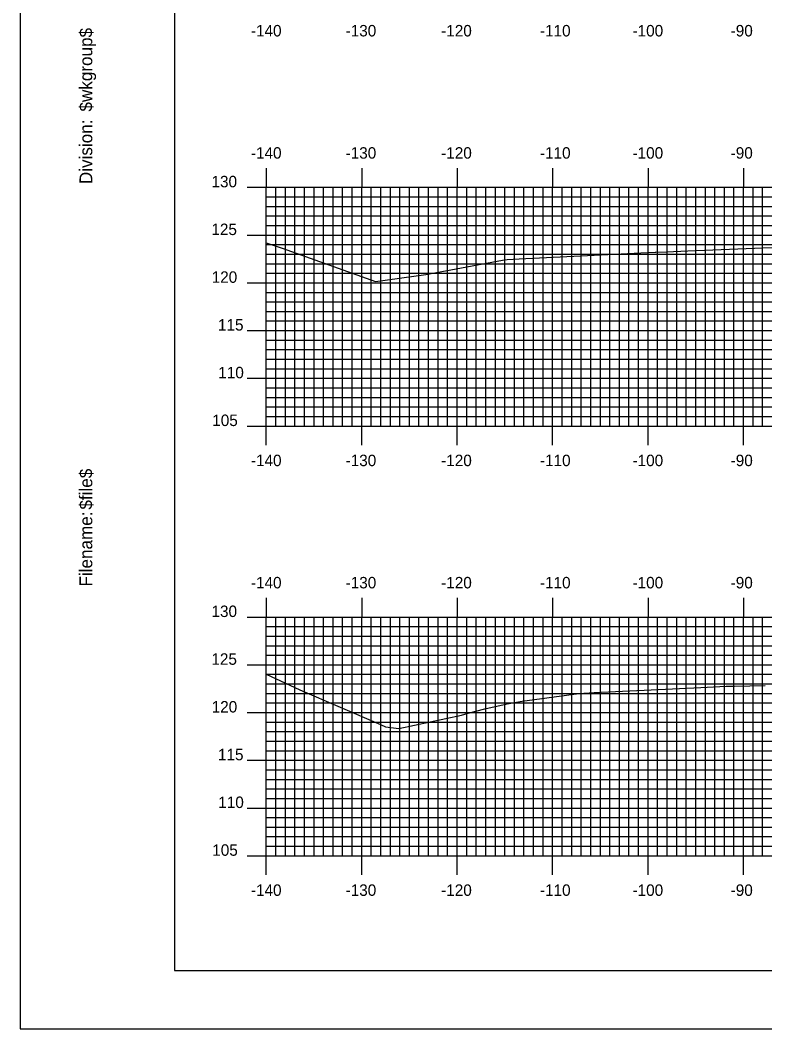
# Model space of a CAD drawing. Extents: x 854287 to 854631, y 366605 to 366825.
# Drawn here: x 854287.3 to 854365.3, y 366604.9 to 366710.6 of the extents above; entities that cross this region are included whole.
import ezdxf

# ---------------------------------------------------------------- set-up
doc = ezdxf.new("R2010")
doc.units = 0
for name, color, linetype in [('BORDER', 7, 'Continuous'), ('H_V ANNOTATION', 7, 'Continuous'), ('M_Roadway_Centerline', 7, 'Continuous'), ('MAJOR', 7, 'Continuous'), ('MINOR', 7, 'Continuous'), ('PLOT BOUNDARY', 7, 'Continuous'), ('S_Roadway_Centerline', 7, 'Continuous')]:
    doc.layers.add(name, color=color, linetype=linetype)

msp = doc.modelspace()

# ---------------------------------------------------------------- linework, layer by layer
at = {"layer": 'BORDER'}
msp.add_lwpolyline([(854303.44, 366611.06), (854623.44, 366611.06), (854623.44, 366821.06), (854303.44, 366821.06)], close=True, dxfattribs=at)
at = {"layer": 'MAJOR'}
for p, q in [((854313.04, 366695.06), (854313.04, 366693.06)), ((854323.04, 366695.06), (854323.04, 366693.06)), ((854333.04, 366695.06), (854333.04, 366693.06)), ((854343.04, 366695.06), (854343.04, 366693.06)), ((854353.04, 366695.06), (854353.04, 366693.06)), ((854363.04, 366695.06), (854363.04, 366693.06)), ((854311.04, 366693.06), (854313.04, 366693.06)), ((854313.04, 366693.06), (854593.04, 366693.06)), ((854313.04, 366668.06), (854313.04, 366693.06)), ((854313.04, 366668.06), (854313.04, 366693.06)), ((854313.04, 366693.06), (854593.04, 366693.06)), ((854323.04, 366668.06), (854323.04, 366693.06)), ((854333.04, 366668.06), (854333.04, 366693.06)), ((854343.04, 366668.06), (854343.04, 366693.06)), ((854353.04, 366668.06), (854353.04, 366693.06)), ((854363.04, 366668.06), (854363.04, 366693.06)), ((854311.04, 366688.06), (854313.04, 366688.06)), ((854313.04, 366688.06), (854593.04, 366688.06)), ((854311.04, 366683.06), (854313.04, 366683.06)), ((854313.04, 366683.06), (854593.04, 366683.06)), ((854311.04, 366678.06), (854313.04, 366678.06)), ((854313.04, 366678.06), (854593.04, 366678.06)), ((854311.04, 366673.06), (854313.04, 366673.06)), ((854313.04, 366673.06), (854593.04, 366673.06)), ((854311.04, 366668.06), (854313.04, 366668.06)), ((854313.04, 366668.06), (854593.04, 366668.06)), ((854313.04, 366668.06), (854593.04, 366668.06)), ((854313.04, 366666.05), (854313.04, 366668.06)), ((854323.04, 366666.05), (854323.04, 366668.06)), ((854333.04, 366666.05), (854333.04, 366668.06)), ((854343.04, 366666.05), (854343.04, 366668.06)), ((854353.04, 366666.05), (854353.04, 366668.06)), ((854363.04, 366666.05), (854363.04, 366668.06)), ((854313.04, 366650.06), (854313.04, 366648.06)), ((854323.04, 366650.06), (854323.04, 366648.06)), ((854333.04, 366650.06), (854333.04, 366648.06)), ((854343.04, 366650.06), (854343.04, 366648.06)), ((854353.04, 366650.06), (854353.04, 366648.06)), ((854363.04, 366650.06), (854363.04, 366648.06)), ((854311.04, 366648.06), (854313.04, 366648.06)), ((854313.04, 366648.06), (854593.04, 366648.06)), ((854313.04, 366623.06), (854313.04, 366648.06)), ((854313.04, 366623.06), (854313.04, 366648.06)), ((854313.04, 366648.06), (854593.04, 366648.06)), ((854323.04, 366623.06), (854323.04, 366648.06)), ((854333.04, 366623.06), (854333.04, 366648.06)), ((854343.04, 366623.06), (854343.04, 366648.06)), ((854353.04, 366623.06), (854353.04, 366648.06)), ((854363.04, 366623.06), (854363.04, 366648.06)), ((854311.04, 366643.06), (854313.04, 366643.06)), ((854313.04, 366643.06), (854593.04, 366643.06)), ((854311.04, 366638.06), (854313.04, 366638.06)), ((854313.04, 366638.06), (854593.04, 366638.06)), ((854311.04, 366633.06), (854313.04, 366633.06)), ((854313.04, 366633.06), (854593.04, 366633.06)), ((854311.04, 366628.06), (854313.04, 366628.06)), ((854313.04, 366628.06), (854593.04, 366628.06)), ((854311.04, 366623.06), (854313.04, 366623.06)), ((854313.04, 366623.06), (854593.04, 366623.06)), ((854313.04, 366623.06), (854593.04, 366623.06)), ((854313.04, 366621.05), (854313.04, 366623.06)), ((854323.04, 366621.05), (854323.04, 366623.06)), ((854333.04, 366621.05), (854333.04, 366623.06)), ((854343.04, 366621.05), (854343.04, 366623.06)), ((854353.04, 366621.05), (854353.04, 366623.06)), ((854363.04, 366621.05), (854363.04, 366623.06))]:
    msp.add_line(p, q, dxfattribs=at)
at = {"layer": 'MINOR'}
for p, q in [((854314.04, 366668.06), (854314.04, 366693.06)), ((854315.04, 366668.06), (854315.04, 366693.06)), ((854316.04, 366668.06), (854316.04, 366693.06)), ((854317.04, 366668.06), (854317.04, 366693.06)), ((854318.04, 366668.06), (854318.04, 366693.06)), ((854319.04, 366668.06), (854319.04, 366693.06)), ((854320.04, 366668.06), (854320.04, 366693.06)), ((854321.04, 366668.06), (854321.04, 366693.06)), ((854322.04, 366668.06), (854322.04, 366693.06)), ((854324.04, 366668.06), (854324.04, 366693.06)), ((854325.04, 366668.06), (854325.04, 366693.06)), ((854326.04, 366668.06), (854326.04, 366693.06)), ((854327.04, 366668.06), (854327.04, 366693.06)), ((854328.04, 366668.06), (854328.04, 366693.06)), ((854329.04, 366668.06), (854329.04, 366693.06)), ((854330.04, 366668.06), (854330.04, 366693.06)), ((854331.04, 366668.06), (854331.04, 366693.06)), ((854332.04, 366668.06), (854332.04, 366693.06)), ((854334.04, 366668.06), (854334.04, 366693.06)), ((854335.04, 366668.06), (854335.04, 366693.06)), ((854336.04, 366668.06), (854336.04, 366693.06)), ((854337.04, 366668.06), (854337.04, 366693.06)), ((854338.04, 366668.06), (854338.04, 366693.06)), ((854339.04, 366668.06), (854339.04, 366693.06)), ((854340.04, 366668.06), (854340.04, 366693.06)), ((854341.04, 366668.06), (854341.04, 366693.06)), ((854342.04, 366668.06), (854342.04, 366693.06)), ((854344.04, 366668.06), (854344.04, 366693.06)), ((854345.04, 366668.06), (854345.04, 366693.06)), ((854346.04, 366668.06), (854346.04, 366693.06)), ((854347.04, 366668.06), (854347.04, 366693.06)), ((854348.04, 366668.06), (854348.04, 366693.06)), ((854349.04, 366668.06), (854349.04, 366693.06)), ((854350.04, 366668.06), (854350.04, 366693.06)), ((854351.04, 366668.06), (854351.04, 366693.06)), ((854352.04, 366668.06), (854352.04, 366693.06)), ((854354.04, 366668.06), (854354.04, 366693.06)), ((854355.04, 366668.06), (854355.04, 366693.06)), ((854356.04, 366668.06), (854356.04, 366693.06)), ((854357.04, 366668.06), (854357.04, 366693.06)), ((854358.04, 366668.06), (854358.04, 366693.06)), ((854359.04, 366668.06), (854359.04, 366693.06)), ((854360.04, 366668.06), (854360.04, 366693.06)), ((854361.04, 366668.06), (854361.04, 366693.06)), ((854362.04, 366668.06), (854362.04, 366693.06)), ((854364.04, 366668.06), (854364.04, 366693.06)), ((854365.04, 366668.06), (854365.04, 366693.06)), ((854313.04, 366692.06), (854593.04, 366692.06)), ((854313.04, 366692.06), (854315.05, 366692.06)), ((854313.04, 366691.06), (854593.04, 366691.06)), ((854313.04, 366691.06), (854315.05, 366691.06)), ((854313.04, 366690.06), (854593.04, 366690.06)), ((854313.04, 366690.06), (854315.05, 366690.06)), ((854313.04, 366689.06), (854593.04, 366689.06)), ((854313.04, 366689.06), (854315.05, 366689.06)), ((854313.04, 366687.06), (854593.04, 366687.06)), ((854313.04, 366687.06), (854315.05, 366687.06)), ((854313.04, 366686.06), (854593.04, 366686.06)), ((854313.04, 366686.06), (854315.05, 366686.06)), ((854313.04, 366685.06), (854593.04, 366685.06)), ((854313.04, 366685.06), (854315.05, 366685.06)), ((854313.04, 366684.06), (854593.04, 366684.06)), ((854313.04, 366684.06), (854315.05, 366684.06)), ((854313.04, 366682.06), (854593.04, 366682.06)), ((854313.04, 366682.06), (854315.05, 366682.06)), ((854313.04, 366681.06), (854593.04, 366681.06)), ((854313.04, 366681.06), (854315.05, 366681.06)), ((854313.04, 366680.06), (854593.04, 366680.06)), ((854313.04, 366680.06), (854315.05, 366680.06)), ((854313.04, 366679.06), (854593.04, 366679.06)), ((854313.04, 366679.06), (854315.05, 366679.06)), ((854313.04, 366677.06), (854593.04, 366677.06)), ((854313.04, 366677.06), (854315.05, 366677.06)), ((854313.04, 366676.06), (854593.04, 366676.06)), ((854313.04, 366676.06), (854315.05, 366676.06)), ((854313.04, 366675.06), (854593.04, 366675.06)), ((854313.04, 366675.06), (854315.05, 366675.06)), ((854313.04, 366674.06), (854593.04, 366674.06)), ((854313.04, 366674.06), (854315.05, 366674.06)), ((854313.04, 366672.06), (854593.04, 366672.06)), ((854313.04, 366672.06), (854315.05, 366672.06)), ((854313.04, 366671.06), (854593.04, 366671.06)), ((854313.04, 366671.06), (854315.05, 366671.06)), ((854313.04, 366670.06), (854593.04, 366670.06)), ((854313.04, 366670.06), (854315.05, 366670.06)), ((854313.04, 366669.06), (854593.04, 366669.06)), ((854313.04, 366669.06), (854315.05, 366669.06)), ((854314.04, 366623.06), (854314.04, 366648.06)), ((854315.04, 366623.06), (854315.04, 366648.06)), ((854316.04, 366623.06), (854316.04, 366648.06)), ((854317.04, 366623.06), (854317.04, 366648.06)), ((854318.04, 366623.06), (854318.04, 366648.06)), ((854319.04, 366623.06), (854319.04, 366648.06)), ((854320.04, 366623.06), (854320.04, 366648.06)), ((854321.04, 366623.06), (854321.04, 366648.06)), ((854322.04, 366623.06), (854322.04, 366648.06)), ((854324.04, 366623.06), (854324.04, 366648.06)), ((854325.04, 366623.06), (854325.04, 366648.06)), ((854326.04, 366623.06), (854326.04, 366648.06)), ((854327.04, 366623.06), (854327.04, 366648.06)), ((854328.04, 366623.06), (854328.04, 366648.06)), ((854329.04, 366623.06), (854329.04, 366648.06)), ((854330.04, 366623.06), (854330.04, 366648.06)), ((854331.04, 366623.06), (854331.04, 366648.06)), ((854332.04, 366623.06), (854332.04, 366648.06)), ((854334.04, 366623.06), (854334.04, 366648.06)), ((854335.04, 366623.06), (854335.04, 366648.06)), ((854336.04, 366623.06), (854336.04, 366648.06)), ((854337.04, 366623.06), (854337.04, 366648.06)), ((854338.04, 366623.06), (854338.04, 366648.06)), ((854339.04, 366623.06), (854339.04, 366648.06)), ((854340.04, 366623.06), (854340.04, 366648.06)), ((854341.04, 366623.06), (854341.04, 366648.06)), ((854342.04, 366623.06), (854342.04, 366648.06)), ((854344.04, 366623.06), (854344.04, 366648.06)), ((854345.04, 366623.06), (854345.04, 366648.06)), ((854346.04, 366623.06), (854346.04, 366648.06)), ((854347.04, 366623.06), (854347.04, 366648.06)), ((854348.04, 366623.06), (854348.04, 366648.06)), ((854349.04, 366623.06), (854349.04, 366648.06)), ((854350.04, 366623.06), (854350.04, 366648.06)), ((854351.04, 366623.06), (854351.04, 366648.06)), ((854352.04, 366623.06), (854352.04, 366648.06)), ((854354.04, 366623.06), (854354.04, 366648.06)), ((854355.04, 366623.06), (854355.04, 366648.06)), ((854356.04, 366623.06), (854356.04, 366648.06)), ((854357.04, 366623.06), (854357.04, 366648.06)), ((854358.04, 366623.06), (854358.04, 366648.06)), ((854359.04, 366623.06), (854359.04, 366648.06)), ((854360.04, 366623.06), (854360.04, 366648.06)), ((854361.04, 366623.06), (854361.04, 366648.06)), ((854362.04, 366623.06), (854362.04, 366648.06)), ((854364.04, 366623.06), (854364.04, 366648.06)), ((854365.04, 366623.06), (854365.04, 366648.06)), ((854313.04, 366647.06), (854593.04, 366647.06)), ((854313.04, 366647.06), (854315.05, 366647.06)), ((854313.04, 366646.06), (854593.04, 366646.06)), ((854313.04, 366646.06), (854315.05, 366646.06)), ((854313.04, 366645.06), (854593.04, 366645.06)), ((854313.04, 366645.06), (854315.05, 366645.06)), ((854313.04, 366644.06), (854593.04, 366644.06)), ((854313.04, 366644.06), (854315.05, 366644.06)), ((854313.04, 366642.06), (854593.04, 366642.06)), ((854313.04, 366642.06), (854315.05, 366642.06)), ((854313.04, 366641.06), (854593.04, 366641.06)), ((854313.04, 366641.06), (854315.05, 366641.06)), ((854313.04, 366640.06), (854593.04, 366640.06)), ((854313.04, 366640.06), (854315.05, 366640.06)), ((854313.04, 366639.06), (854593.04, 366639.06)), ((854313.04, 366639.06), (854315.05, 366639.06)), ((854313.04, 366637.06), (854593.04, 366637.06)), ((854313.04, 366637.06), (854315.05, 366637.06)), ((854313.04, 366636.06), (854593.04, 366636.06)), ((854313.04, 366636.06), (854315.05, 366636.06)), ((854313.04, 366635.06), (854593.04, 366635.06)), ((854313.04, 366635.06), (854315.05, 366635.06)), ((854313.04, 366634.06), (854593.04, 366634.06)), ((854313.04, 366634.06), (854315.05, 366634.06)), ((854313.04, 366632.06), (854593.04, 366632.06)), ((854313.04, 366632.06), (854315.05, 366632.06)), ((854313.04, 366631.06), (854593.04, 366631.06)), ((854313.04, 366631.06), (854315.05, 366631.06)), ((854313.04, 366630.06), (854593.04, 366630.06)), ((854313.04, 366630.06), (854315.05, 366630.06)), ((854313.04, 366629.06), (854593.04, 366629.06)), ((854313.04, 366629.06), (854315.05, 366629.06)), ((854313.04, 366627.06), (854593.04, 366627.06)), ((854313.04, 366627.06), (854315.05, 366627.06)), ((854313.04, 366626.06), (854593.04, 366626.06)), ((854313.04, 366626.06), (854315.05, 366626.06)), ((854313.04, 366625.06), (854593.04, 366625.06)), ((854313.04, 366625.06), (854315.05, 366625.06)), ((854313.04, 366624.06), (854593.04, 366624.06)), ((854313.04, 366624.06), (854315.05, 366624.06))]:
    msp.add_line(p, q, dxfattribs=at)
at = {"layer": 'PLOT BOUNDARY'}
msp.add_lwpolyline([(854287.26, 366604.94), (854627.26, 366604.94), (854627.26, 366824.94), (854287.26, 366824.94)], close=True, dxfattribs=at)
at = {"layer": 'S_Roadway_Centerline'}
for points in [[(854313.04, 366687.23), (854314.7, 366686.68), (854324.47, 366683.2), (854329.74, 366683.92), (854337.78, 366685.44), (854338.28, 366685.51), (854339.55, 366685.57), (854348.82, 366686.03), (854352.27, 366686.2), (854353.77, 366686.28), (854353.86, 366686.28), (854354.96, 366686.32), (854357.22, 366686.41), (854365.05, 366686.71), (854366.98, 366686.79)], [(854313.04, 366642.06), (854316.55, 366640.44), (854325.01, 366636.82), (854325.52, 366636.57), (854326.94, 366636.38), (854333.51, 366637.8), (854334.19, 366638), (854335.95, 366638.45), (854338.29, 366638.96), (854339.85, 366639.24), (854345.79, 366640.06), (854347.4, 366640.15), (854355.6, 366640.53), (854358.55, 366640.67), (854361.21, 366640.81), (854362.11, 366640.81), (854365.29, 366640.89)]]:
    msp.add_lwpolyline(points, dxfattribs=at)

# ---------------------------------------------------------------- texts
at = {"layer": 'BORDER'}
for s, p in [('$wkgroup$', (854294.81, 366700.99)), ('Division:', (854294.81, 366693.39)), ('$file$', (854294.81, 366659.31)), ('Filename:', (854294.81, 366651.25))]:
    msp.add_text(s, height=1.339, rotation=90, dxfattribs=at).set_placement(p)
at = {"layer": 'H_V ANNOTATION'}
for s, p in [('-140', (854311.43, 366708.86)), ('-130', (854321.35, 366708.86)), ('-120', (854331.36, 366708.86)), ('-110', (854341.71, 366708.86)), ('-100', (854351.41, 366708.86)), ('-90', (854361.69, 366708.86)), ('-140', (854311.43, 366696.06)), ('-130', (854321.35, 366696.06)), ('-120', (854331.36, 366696.06)), ('-110', (854341.71, 366696.06)), ('-100', (854351.41, 366696.06)), ('-90', (854361.69, 366696.06)), ('130', (854307.3, 366693.06)), ('125', (854307.29, 366688.06)), ('120', (854307.32, 366683.06)), ('115', (854307.98, 366678.06)), ('110', (854308.01, 366673.06)), ('105', (854307.38, 366668.06)), ('-140', (854311.43, 366663.86)), ('-130', (854321.35, 366663.86)), ('-120', (854331.36, 366663.86)), ('-110', (854341.71, 366663.86)), ('-100', (854351.41, 366663.86)), ('-90', (854361.69, 366663.86)), ('-140', (854311.43, 366651.06)), ('-130', (854321.35, 366651.06)), ('-120', (854331.36, 366651.06)), ('-110', (854341.71, 366651.06)), ('-100', (854351.41, 366651.06)), ('-90', (854361.69, 366651.06)), ('130', (854307.3, 366648.06)), ('125', (854307.29, 366643.06)), ('120', (854307.32, 366638.06)), ('115', (854307.98, 366633.06)), ('110', (854308.01, 366628.06)), ('105', (854307.38, 366623.06)), ('-140', (854311.43, 366618.86)), ('-130', (854321.35, 366618.86)), ('-120', (854331.36, 366618.86)), ('-110', (854341.71, 366618.86)), ('-100', (854351.41, 366618.86)), ('-90', (854361.69, 366618.86))]:
    msp.add_text(s, height=1.2, dxfattribs=at).set_placement(p)
at = {"layer": 'M_Roadway_Centerline'}
for s, p in [('C', (854353.85, 366686.28)), ('L', (854353.86, 366686.27)), ('C', (854361.2, 366640.81)), ('L', (854361.21, 366640.81))]:
    msp.add_text(s, height=0.0146, dxfattribs=at).set_placement(p)
at = {"layer": 'MAJOR'}
for p in [(854313.03, 366668.06), (854313.03, 366623.06)]:
    msp.add_text('-', height=0.012, dxfattribs=at).set_placement(p)

doc.saveas('drawing.dxf')
